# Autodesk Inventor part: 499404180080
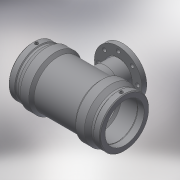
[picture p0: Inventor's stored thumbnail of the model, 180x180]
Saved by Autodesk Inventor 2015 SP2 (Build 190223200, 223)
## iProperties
Created: 2017-06
Part Number: 499404180080
Material: Generic
Description: PLASSON FLANGED TEE 180x80x180
Document SubType Name: Modeling
Designer: KIM
Mass: 57.3761 g
Surface Area: 241.06 cm^2
Volume: 57.3761 cm^3
Density: 1 g/cm^3
Appearance: Default
Author: KIM
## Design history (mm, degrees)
derived "499404.ipt"
feature "Solid1::499404.ipt"
tag "TaggingFeature1"
body "Solid1"
other parameters: "d13" = 422, "d14" = 17.6296, "d17" = 162, "d19" = 3.52592, "d20" = 168 deg, "d22" = 227.85, "d23" = 245, "d24" = 221.0145, "d25" = 135 deg, "d26" = 295.4, "d27" = 135 deg, "d29" = 116, "d35" = 15, "d39" = 5 deg, "d45" = 4, "d46" = 14, "d47" = 0, "d48" = -225, "d55" = 220.5, "d56" = 245, "d57" = 147.7, "d58" = 135 deg, "d59" = 106, "d60" = 106, "d61" = 135 deg, "d62" = 225, "d72" = 192.01, "d73" = 96.005, "d74" = -225, "d84" = 225, "d87" = 138, "d89" = 96, "d91" = 15 deg, "d92" = 104, "d95" = 4.14, "d97" = 18, "d100" = 0, "d102" = 360 deg, "d105" = 0, "d107" = 0, "d108" = 3, "d109" = 0, "d110" = 31.8, "d111" = 10.6, "L_" = 422, "L_1" = 106, "D_" = 245, "A_" = 116, "d_2" = 12, "H_" = 225, "d_1" = 138, "s_" = 18
